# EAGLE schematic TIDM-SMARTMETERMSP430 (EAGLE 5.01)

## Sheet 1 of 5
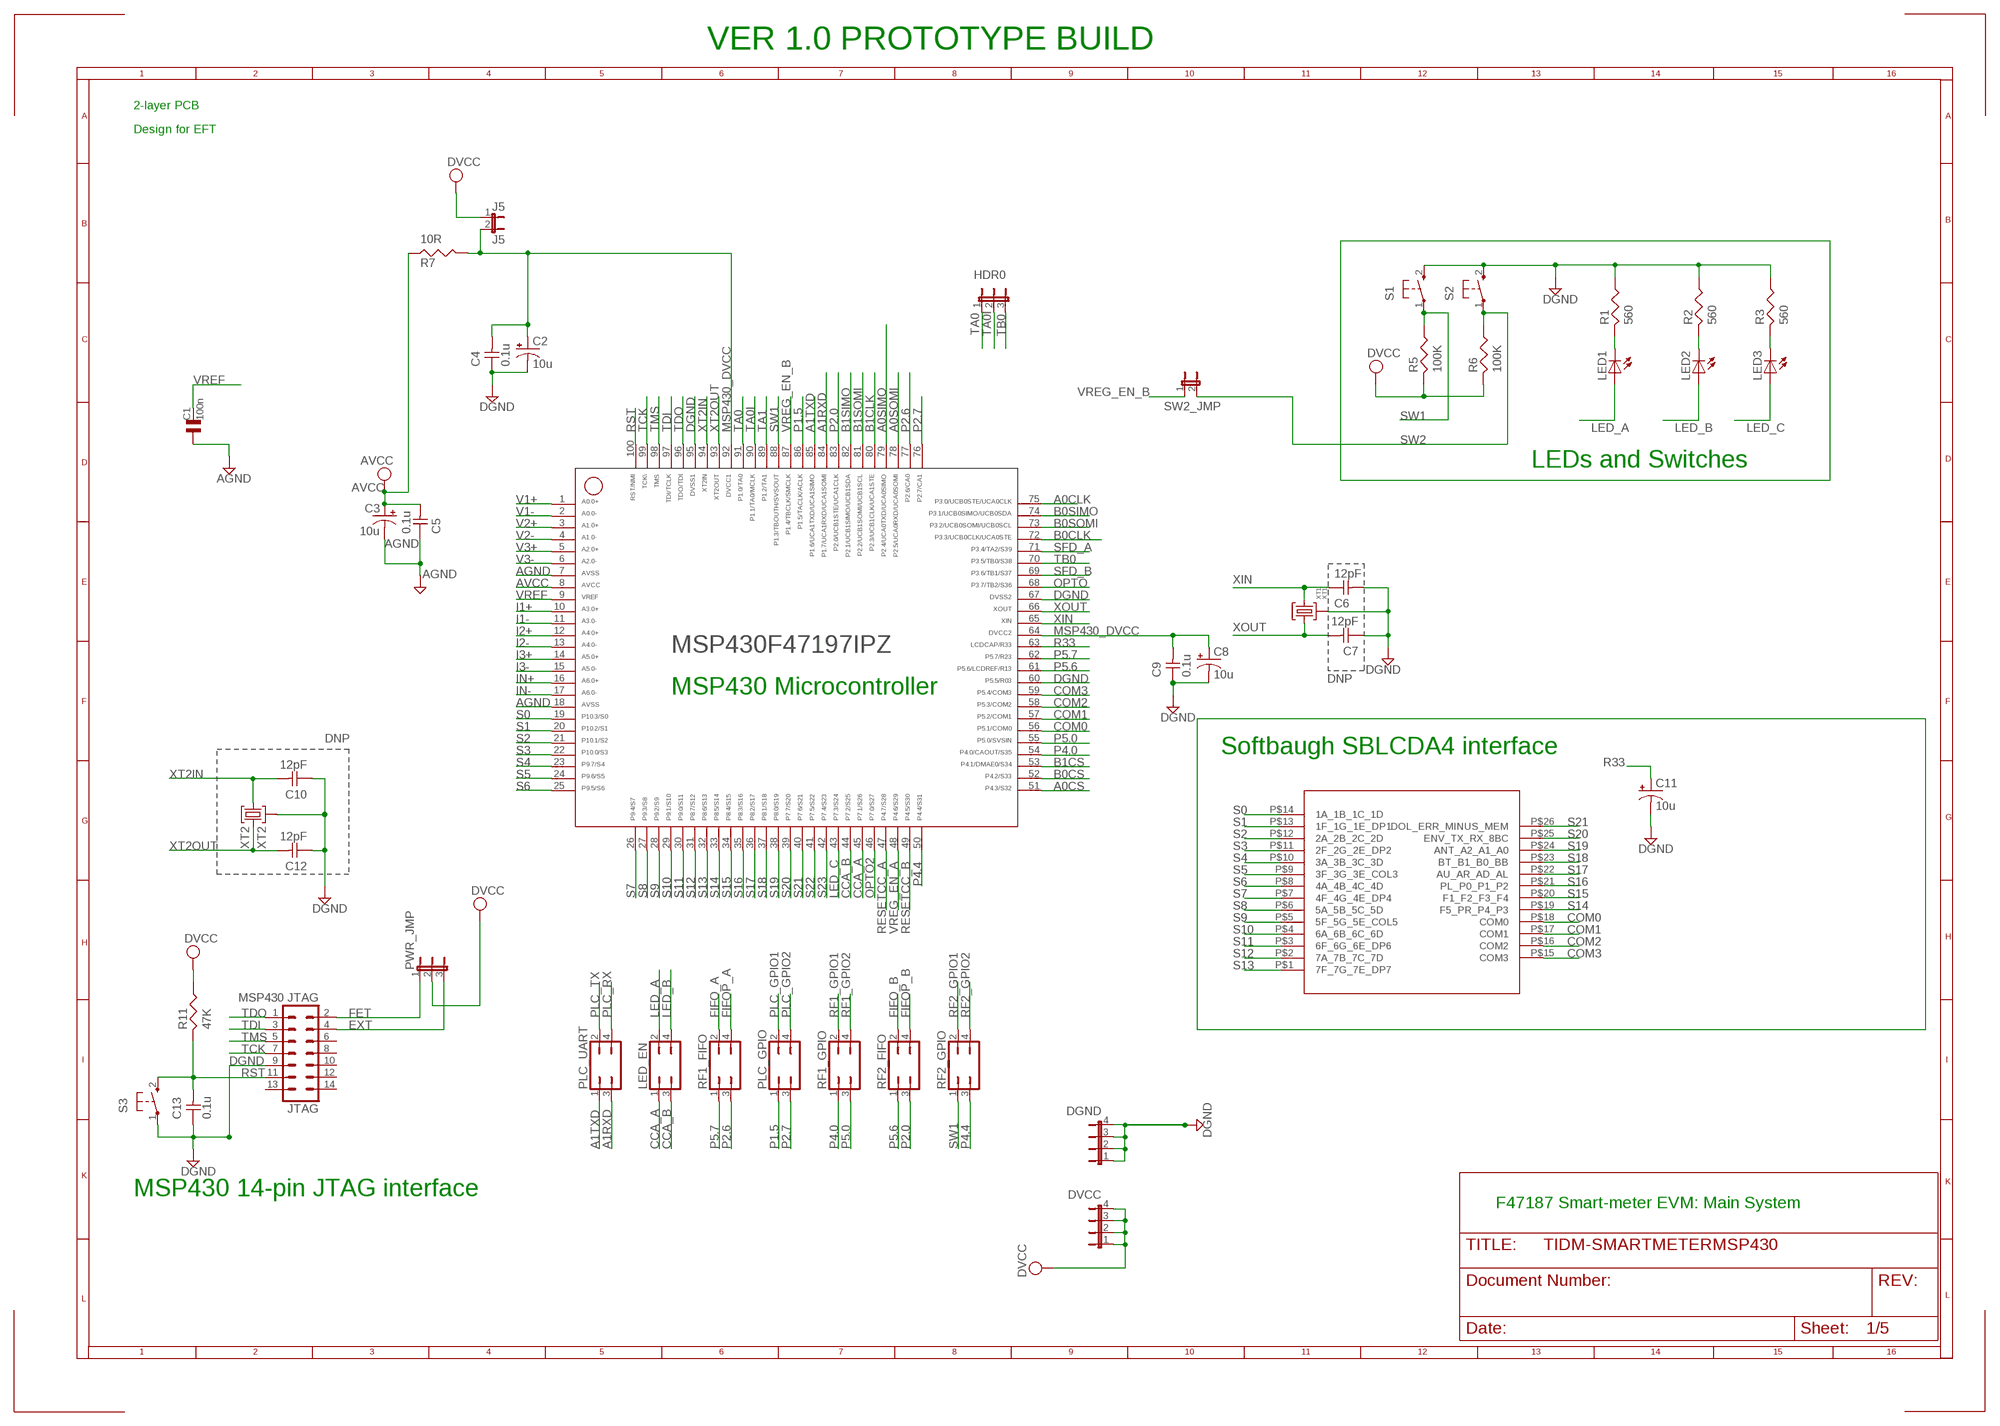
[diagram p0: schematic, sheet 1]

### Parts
C1  100n  C  [0805]
C2  10u  CPOL-USCT3216  [CT3216]
C3  10u  CPOL-USCT3216  [CT3216]
C4  0.1u  CAP-NP0805  [C0805]
C5  0.1u  CAP-NP0805  [C0805]
C6  12pF  CAP-NP0805  [C0805]
C7  12pF  CAP-NP0805  [C0805]
C8  10u  CPOL-USCT3216  [CT3216]
C9  0.1u  CAP-NP0805  [C0805]
C10  12pF  CAP-NP0805  [C0805]
C11  10u  CPOL-USCT3216  [CT3216]
C12  12pF  CAP-NP0805  [C0805]
C13  0.1u  CAP-NP0805  [C0805]
DGND  GND_JMP  JP4E  [JP4]
DVCC  JP4E  [JP4]
HDR0  JP2E  [JP2]
J5  J5  JP1E  [JP1]
JTAG  MSP430 JTAG  ML14  [ML14]
LCD1  SBLCDA4  [SBLCDA4]
LED1  LEDCHIPLED_0805  [CHIPLED_0805]
LED2  LEDCHIPLED_0805  [CHIPLED_0805]
LED3  LEDCHIPLED_0805  [CHIPLED_0805]
LED_EN  JP2Q  [JP2Q]
MSP430F47187  MSP430F471X7PZ100  [PZ100]
PLC_GPIO  JP2Q  [JP2Q]
PLC_UART  JP2Q  [JP2Q]
PWR_JMP  JP2E  [JP2]
R1  560  RES0805  [R0805]
R2  560  RES0805  [R0805]
R3  560  RES0805  [R0805]
R5  100K  RES0805  [R0805]
R6  100K  RES0805  [R0805]
R7  10R  RES0805  [R0805]
R11  47K  RES0805  [R0805]
RF1_FIFO  JP2Q  [JP2Q]
RF1_GPIO  JP2Q  [JP2Q]
RF2_FIFO  JP2Q  [JP2Q]
RF2_GPIO  JP2Q  [JP2Q]
S1  PB  [PBTH]
S2  PB  [PBTH]
S3  PB  [PBTH]
SW2_JMP  JP1E  [JP1]
XT1  XT1  CM200T  [CM200T]
XT2  XT2  X905  [X905]

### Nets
A0CLK: MSP430F47187.75 ; also sheet 4
A0CS: MSP430F47187.51 ; also sheet 4
A0SIMO: MSP430F47187.79 ; also sheet 4
A0SOMI: MSP430F47187.78 ; also sheet 4
A1RXD: MSP430F47187.84 PLC_UART.3 ; also sheet 4
A1TXD: MSP430F47187.85 PLC_UART.1 ; also sheet 4
AGND: C1.1 C3.- C5.1 MSP430F47187.7 MSP430F47187.18 ; also sheet 2
AVCC: C3.+ C5.2 MSP430F47187.8 R7.2 ; also sheet 2
B0CLK: MSP430F47187.72 ; also sheet 4
B0CS: MSP430F47187.52 ; also sheet 4
B0SIMO: MSP430F47187.74 ; also sheet 4
B0SOMI: MSP430F47187.73 ; also sheet 4
B1CLK: MSP430F47187.80 ; also sheet 5
B1CS: MSP430F47187.53 ; also sheet 5
B1SIMO: MSP430F47187.82 ; also sheet 5
B1SOMI: MSP430F47187.81 ; also sheet 5
CCA_A: LED_EN.1 MSP430F47187.45 ; also sheet 4
CCA_B: LED_EN.3 MSP430F47187.44 ; also sheet 4
COM0: LCD1.P$18(COM0) MSP430F47187.56
COM1: LCD1.P$17(COM1) MSP430F47187.57
COM2: LCD1.P$16(COM2) MSP430F47187.58
COM3: LCD1.P$15(COM3) MSP430F47187.59
DGND: C2.- C4.1 C6.2 C7.1 C8.- C9.1 C10.1 C11.- C12.1 C13.1 DGND.1 DGND.2 DGND.3 DGND.4 JTAG.9 MSP430F47187.60 MSP430F47187.67 MSP430F47187.95 R1.1 R2.1 R3.1 S1.2(S) S2.2(S) S3.1(P) XT1.P3 XT2.2 ; also sheet 3,4,5
DVCC: DVCC.1 DVCC.2 DVCC.3 DVCC.4 J5.1 PWR_JMP.2 R5.2 R6.2 R11.1 ; also sheet 3,4,5
EXT: JTAG.4 PWR_JMP.3
FET: JTAG.2 PWR_JMP.1
FIFO_A: RF1_FIFO.2 ; also sheet 4
FIFO_B: RF2_FIFO.2 ; also sheet 4
FIFOP_A: RF1_FIFO.4 ; also sheet 4
FIFOP_B: RF2_FIFO.4 ; also sheet 4
I1+: MSP430F47187.10 ; also sheet 2
I1-: MSP430F47187.11 ; also sheet 2
I2+: MSP430F47187.12 ; also sheet 2
I2-: MSP430F47187.13 ; also sheet 2
I3+: MSP430F47187.14 ; also sheet 2
I3-: MSP430F47187.15 ; also sheet 2
IN+: MSP430F47187.16 ; also sheet 2
IN-: MSP430F47187.17 ; also sheet 2
LED_A: LED1.A LED_EN.2
LED_B: LED2.A LED_EN.4
LED_C: LED3.A MSP430F47187.43
MSP430_DVCC: C2.+ C4.2 C8.+ C9.2 J5.2 MSP430F47187.64 MSP430F47187.92 R7.1
N$4: LED1.C R1.2
N$7: LED2.C R2.2
N$30: LED3.C R3.2
OPTO: MSP430F47187.68 ; also sheet 4
OPTO2: MSP430F47187.46 ; also sheet 4
P1.5: MSP430F47187.86 PLC_GPIO.1
P2.0: MSP430F47187.83 RF2_FIFO.3
P2.6: MSP430F47187.77 RF1_FIFO.3
P2.7: MSP430F47187.76 PLC_GPIO.3
P4.0: MSP430F47187.54 RF1_GPIO.1
P4.4: MSP430F47187.50 RF2_GPIO.3
P5.0: MSP430F47187.55 RF1_GPIO.3
P5.6: MSP430F47187.61 RF2_FIFO.1
P5.7: MSP430F47187.62 RF1_FIFO.1
PLC_GPIO1: PLC_GPIO.2 ; also sheet 5
PLC_GPIO2: PLC_GPIO.4 ; also sheet 5
PLC_RX: PLC_UART.4 ; also sheet 3,4,5
PLC_TX: PLC_UART.2 ; also sheet 3,4,5
R33: C11.+ MSP430F47187.63
RESETCC_A: MSP430F47187.47 ; also sheet 4
RESETCC_B: MSP430F47187.49 ; also sheet 4
RF1_GPIO1: RF1_GPIO.2 ; also sheet 4
RF1_GPIO2: RF1_GPIO.4 ; also sheet 4
RF2_GPIO1: RF2_GPIO.2 ; also sheet 4
RF2_GPIO2: RF2_GPIO.4 ; also sheet 4
RST: C13.2 JTAG.11 MSP430F47187.100 R11.2 S3.2(S)
S0: LCD1.P$14(1A_1B_1C_1D) MSP430F47187.19
S1: LCD1.P$13(1F_1G_1E_DP1) MSP430F47187.20
S2: LCD1.P$12(2A_2B_2C_2D) MSP430F47187.21
S3: LCD1.P$11(2F_2G_2E_DP2) MSP430F47187.22
S4: LCD1.P$10(3A_3B_3C_3D) MSP430F47187.23
S5: LCD1.P$9(3F_3G_3E_COL3) MSP430F47187.24
S6: LCD1.P$8(4A_4B_4C_4D) MSP430F47187.25
S7: LCD1.P$7(4F_4G_4E_DP4) MSP430F47187.26
S8: LCD1.P$6(5A_5B_5C_5D) MSP430F47187.27
S9: LCD1.P$5(5F_5G_5E_COL5) MSP430F47187.28
S10: LCD1.P$4(6A_6B_6C_6D) MSP430F47187.29
S11: LCD1.P$3(6F_6G_6E_DP6) MSP430F47187.30
S12: LCD1.P$2(7A_7B_7C_7D) MSP430F47187.31
S13: LCD1.P$1(7F_7G_7E_DP7) MSP430F47187.32
S14: LCD1.P$19(F5_PR_P4_P3) MSP430F47187.33
S15: LCD1.P$20(F1_F2_F3_F4) MSP430F47187.34
S16: LCD1.P$21(PL_P0_P1_P2) MSP430F47187.35
S17: LCD1.P$22(AU_AR_AD_AL) MSP430F47187.36
S18: LCD1.P$23(BT_B1_B0_BB) MSP430F47187.37
S19: LCD1.P$24(ANT_A2_A1_A0) MSP430F47187.38
S20: LCD1.P$25(ENV_TX_RX_8BC) MSP430F47187.39
S21: LCD1.P$26(DOL_ERR_MINUS_MEM) MSP430F47187.40
S22: MSP430F47187.41
S23: MSP430F47187.42
SFD_A: MSP430F47187.71 ; also sheet 4
SFD_B: MSP430F47187.69 ; also sheet 4
SW1: MSP430F47187.88 R5.1 RF2_GPIO.1 S1.1(P)
SW2: R6.1 S2.1(P) SW2_JMP.2
TA0: HDR0.1 MSP430F47187.91
TA0I: HDR0.2 MSP430F47187.90
TA1: MSP430F47187.89 ; also sheet 5
TB0: HDR0.3 MSP430F47187.70
TCK: JTAG.7 MSP430F47187.99
TDI: JTAG.3 MSP430F47187.97
TDO: JTAG.1 MSP430F47187.96
TMS: JTAG.5 MSP430F47187.98
V1+: MSP430F47187.1 ; also sheet 2
V1-: MSP430F47187.2 ; also sheet 2
V2+: MSP430F47187.3 ; also sheet 2
V2-: MSP430F47187.4 ; also sheet 2
V3+: MSP430F47187.5 ; also sheet 2
V3-: MSP430F47187.6 ; also sheet 2
VREF: C1.2 MSP430F47187.9 ; also sheet 2
VREG_EN_A: MSP430F47187.48 ; also sheet 4
VREG_EN_B: MSP430F47187.87 SW2_JMP.1 ; also sheet 4
XIN: C6.1 MSP430F47187.65 XT1.P2
XOUT: C7.2 MSP430F47187.66 XT1.P1
XT2IN: C10.2 MSP430F47187.94 XT2.1
XT2OUT: C12.2 MSP430F47187.93 XT2.3
Unconnected: JTAG.6 JTAG.8 JTAG.10 JTAG.12 JTAG.13 JTAG.14

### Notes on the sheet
- VER 1.0 PROTOTYPE BUILD
- 2-layer PCB
- Design for EFT
- LEDs and Switches
- DNP
- MSP430 Microcontroller
- DNP
- Softbaugh SBLCDA4 interface
- MSP430 14-pin JTAG interface
- F47187 Smart-meter EVM: Main System

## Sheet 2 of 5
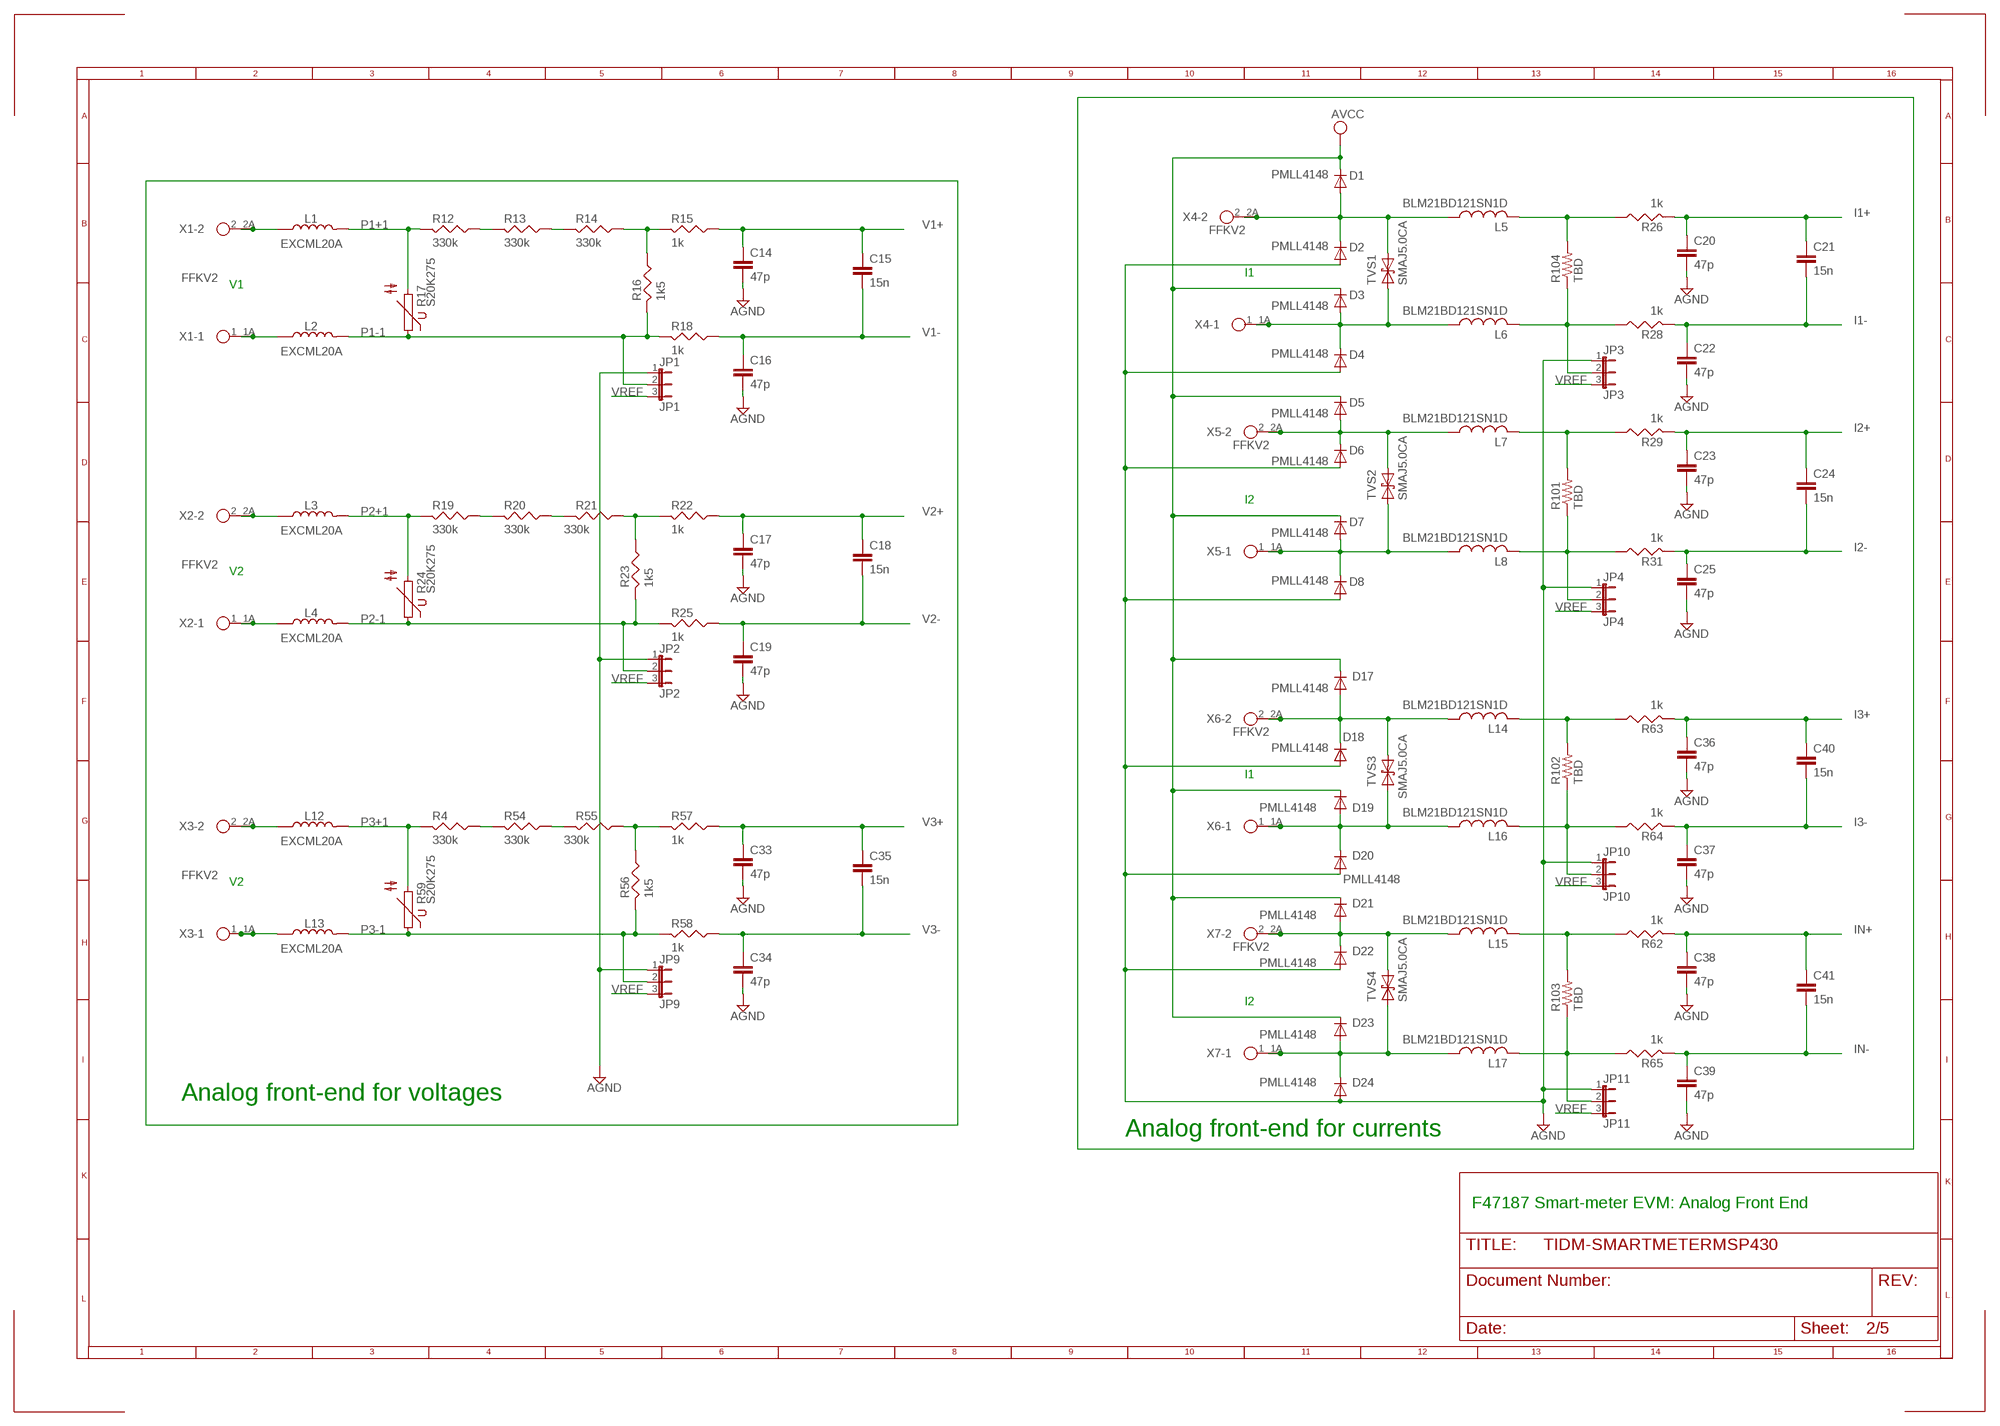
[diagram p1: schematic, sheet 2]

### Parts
C14  47p  C-EUC0805  [C0805]
C15  15n  C-EUC0805  [C0805]
C16  47p  C-EUC0805  [C0805]
C17  47p  C-EUC0805  [C0805]
C18  15n  C-EUC0805  [C0805]
C19  47p  C-EUC0805  [C0805]
C20  47p  C-EUC0805  [C0805]
C21  15n  C-EUC0805  [C0805]
C22  47p  C-EUC0805  [C0805]
C23  47p  C-EUC0805  [C0805]
C24  15n  C-EUC0805  [C0805]
C25  47p  C-EUC0805  [C0805]
C33  47p  C-EUC0805  [C0805]
C34  47p  C-EUC0805  [C0805]
C35  15n  C-EUC0805  [C0805]
C36  47p  C-EUC0805  [C0805]
C37  47p  C-EUC0805  [C0805]
C38  47p  C-EUC0805  [C0805]
C39  47p  C-EUC0805  [C0805]
C40  15n  C-EUC0805  [C0805]
C41  15n  C-EUC0805  [C0805]
D1  PMLL4148  [SOD80C]
D2  PMLL4148  [SOD80C]
D3  PMLL4148  [SOD80C]
D4  PMLL4148  [SOD80C]
D5  PMLL4148  [SOD80C]
D6  PMLL4148  [SOD80C]
D7  PMLL4148  [SOD80C]
D8  PMLL4148  [SOD80C]
D17  PMLL4148  [SOD80C]
D18  PMLL4148  [SOD80C]
D19  PMLL4148  [SOD80C]
D20  PMLL4148  [SOD80C]
D21  PMLL4148  [SOD80C]
D22  PMLL4148  [SOD80C]
D23  PMLL4148  [SOD80C]
D24  PMLL4148  [SOD80C]
JP1  JP1  JP2E  [JP2]
JP2  JP2  JP2E  [JP2]
JP3  JP3  JP2E  [JP2]
JP4  JP4  JP2E  [JP2]
JP9  JP9  JP2E  [JP2]
JP10  JP10  JP2E  [JP2]
JP11  JP11  JP2E  [JP2]
L1  EXCML20A  EXCELSA390805  [R0805]
L2  EXCML20A  EXCELSA390805  [R0805]
L3  EXCML20A  EXCELSA390805  [R0805]
L4  EXCML20A  EXCELSA390805  [R0805]
L5  BLM21BD121SN1D  L-US08050805  [0805]
L6  BLM21BD121SN1D  L-US08050805  [0805]
L7  BLM21BD121SN1D  L-US08050805  [0805]
L8  BLM21BD121SN1D  L-US08050805  [0805]
L12  EXCML20A  EXCELSA390805  [R0805]
L13  EXCML20A  EXCELSA390805  [R0805]
L14  BLM21BD121SN1D  L-US08050805  [0805]
L15  BLM21BD121SN1D  L-US08050805  [0805]
L16  BLM21BD121SN1D  L-US08050805  [0805]
L17  BLM21BD121SN1D  L-US08050805  [0805]
R4  330k  RES0805  [R0805]
R12  330k  RES0805  [R0805]
R13  330k  RES0805  [R0805]
R14  330k  RES0805  [R0805]
R15  1k  RES0805  [R0805]
R16  1k5  RES0805  [R0805]
R17  S20K275  [S20K275]
R18  1k  RES0805  [R0805]
R19  330k  RES0805  [R0805]
R20  330k  RES0805  [R0805]
R21  330k  RES0805  [R0805]
R22  1k  RES0805  [R0805]
R23  1k5  RES0805  [R0805]
R24  S20K275  [S20K275]
R25  1k  RES0805  [R0805]
R26  1k  RES0805  [R0805]
R28  1k  RES0805  [R0805]
R29  1k  RES0805  [R0805]
R31  1k  RES0805  [R0805]
R54  330k  RES0805  [R0805]
R55  330k  RES0805  [R0805]
R56  1k5  RES0805  [R0805]
R57  1k  RES0805  [R0805]
R58  1k  RES0805  [R0805]
R59  S20K275  [S20K275]
R62  1k  RES0805  [R0805]
R63  1k  RES0805  [R0805]
R64  1k  RES0805  [R0805]
R65  1k  RES0805  [R0805]
R101  TBD  R-US_0207/2V  [0207/2V]
R102  TBD  R-US_0207/2V  [0207/2V]
R103  TBD  R-US_0207/2V  [0207/2V]
R104  TBD  R-US_0207/2V  [0207/2V]
TVS1  SMAJ5.0CA  [DO214AC]
TVS2  SMAJ5.0CA  [DO214AC]
TVS3  SMAJ5.0CA  [DO214AC]
TVS4  SMAJ5.0CA  [DO214AC]
X1  FFKV2  [FFKV2]
X2  FFKV2  [FFKV2]
X3  FFKV2  [FFKV2]
X4  FFKV2  [FFKV2]
X5  FFKV2  [FFKV2]
X6  FFKV2  [FFKV2]
X7  FFKV2  [FFKV2]

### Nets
AGND: C14.2 C16.2 C17.2 C19.2 C20.2 C22.2 C23.2 C25.2 C33.2 C34.2 C36.2 C37.2 C38.2 C39.2 D2.A D4.A D6.A D8.A D18.A D20.A D22.A D24.A JP1.1 JP2.1 JP3.1 JP4.1 JP9.1 JP10.1 JP11.1 ; also sheet 1
AVCC: D1.C D3.C D5.C D7.C D17.C D19.C D21.C D23.C ; also sheet 1
I1+: C20.1 C21.1 R26.2 ; also sheet 1
I1-: C21.2 C22.1 R28.2 ; also sheet 1
I2+: C23.1 C24.1 R29.2 ; also sheet 1
I2-: C24.2 C25.1 R31.2 ; also sheet 1
I3+: C36.1 C40.1 R63.2 ; also sheet 1
I3-: C37.1 C40.2 R64.2 ; also sheet 1
IN+: C38.1 C41.1 R62.2 ; also sheet 1
IN-: C39.1 C41.2 R65.2 ; also sheet 1
IS1+: D1.A D2.C L5.1 TVS1.C(K) X4.2 X4.2A
IS2+: D5.A D6.C L7.1 TVS2.C(K) X5.2 X5.2A
N$8: R12.1 R13.2
N$13: R13.1 R14.2
N$14: R14.1 R15.2 R16.1
N$15: R19.1 R20.2
N$16: R20.1 R21.2
N$19: R21.1 R22.2 R23.1
N$27: R4.1 R54.2
N$28: R54.1 R55.2
N$29: R55.1 R56.1 R57.2
N$31: L7.2 R29.1 R101.2
N$32: L5.2 R26.1 R104.2
N$33: L15.2 R62.1 R103.2
N$34: L14.2 R63.1 R102.2
N$35: JP10.2 L16.2 R64.1 R102.1
N$36: JP11.2 L17.2 R65.1 R103.1
N$41: D3.A D4.C L6.1 TVS1.A X4.1 X4.1A
N$43: D23.A D24.C L17.1 TVS4.A X7.1 X7.1A
N$47: D17.A D18.C L14.1 TVS3.C(K) X6.2 X6.2A
N$48: D7.A D8.C L8.1 TVS2.A X5.1 X5.1A
N$49: D19.A D20.C L16.1 TVS3.A X6.1 X6.1A
N$72: D21.A D22.C L15.1 TVS4.C(K) X7.2 X7.2A
N$202: JP3.2 L6.2 R28.1 R104.1
N$229: JP4.2 L8.2 R31.1 R101.1
P1+: L1.1 X1.2 X1.2A
P1+1: L1.2 R12.2 R17.2 ; also sheet 3,5
P1-: L2.1 X1.1 X1.1A
P1-1: JP1.2 L2.2 R16.2 R17.1 R18.2 ; also sheet 3,5
P2+: L3.1 X2.2 X2.2A
P2+1: L3.2 R19.2 R24.2 ; also sheet 5
P2-: L4.1 X2.1 X2.1A
P2-1: JP2.2 L4.2 R23.2 R24.1 R25.2
P3+: L12.1 X3.2 X3.2A
P3+1: L12.2 R4.2 R59.2 ; also sheet 5
P3-: L13.1 X3.1 X3.1A
P3-1: JP9.2 L13.2 R56.2 R58.2 R59.1
V1+: C14.1 C15.1 R15.1 ; also sheet 1
V1-: C15.2 C16.1 R18.1 ; also sheet 1
V2+: C17.1 C18.1 R22.1 ; also sheet 1
V2-: C18.2 C19.1 R25.1 ; also sheet 1
V3+: C33.1 C35.1 R57.1 ; also sheet 1
V3-: C34.1 C35.2 R58.1 ; also sheet 1
VREF: JP1.3 JP2.3 JP3.3 JP4.3 JP9.3 JP10.3 JP11.3 ; also sheet 1

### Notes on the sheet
- I1
- V1
- I2
- V2
- I1
- V2
- I2
- Analog front-end for voltages
- Analog front-end for currents
- F47187 Smart-meter EVM: Analog Front End

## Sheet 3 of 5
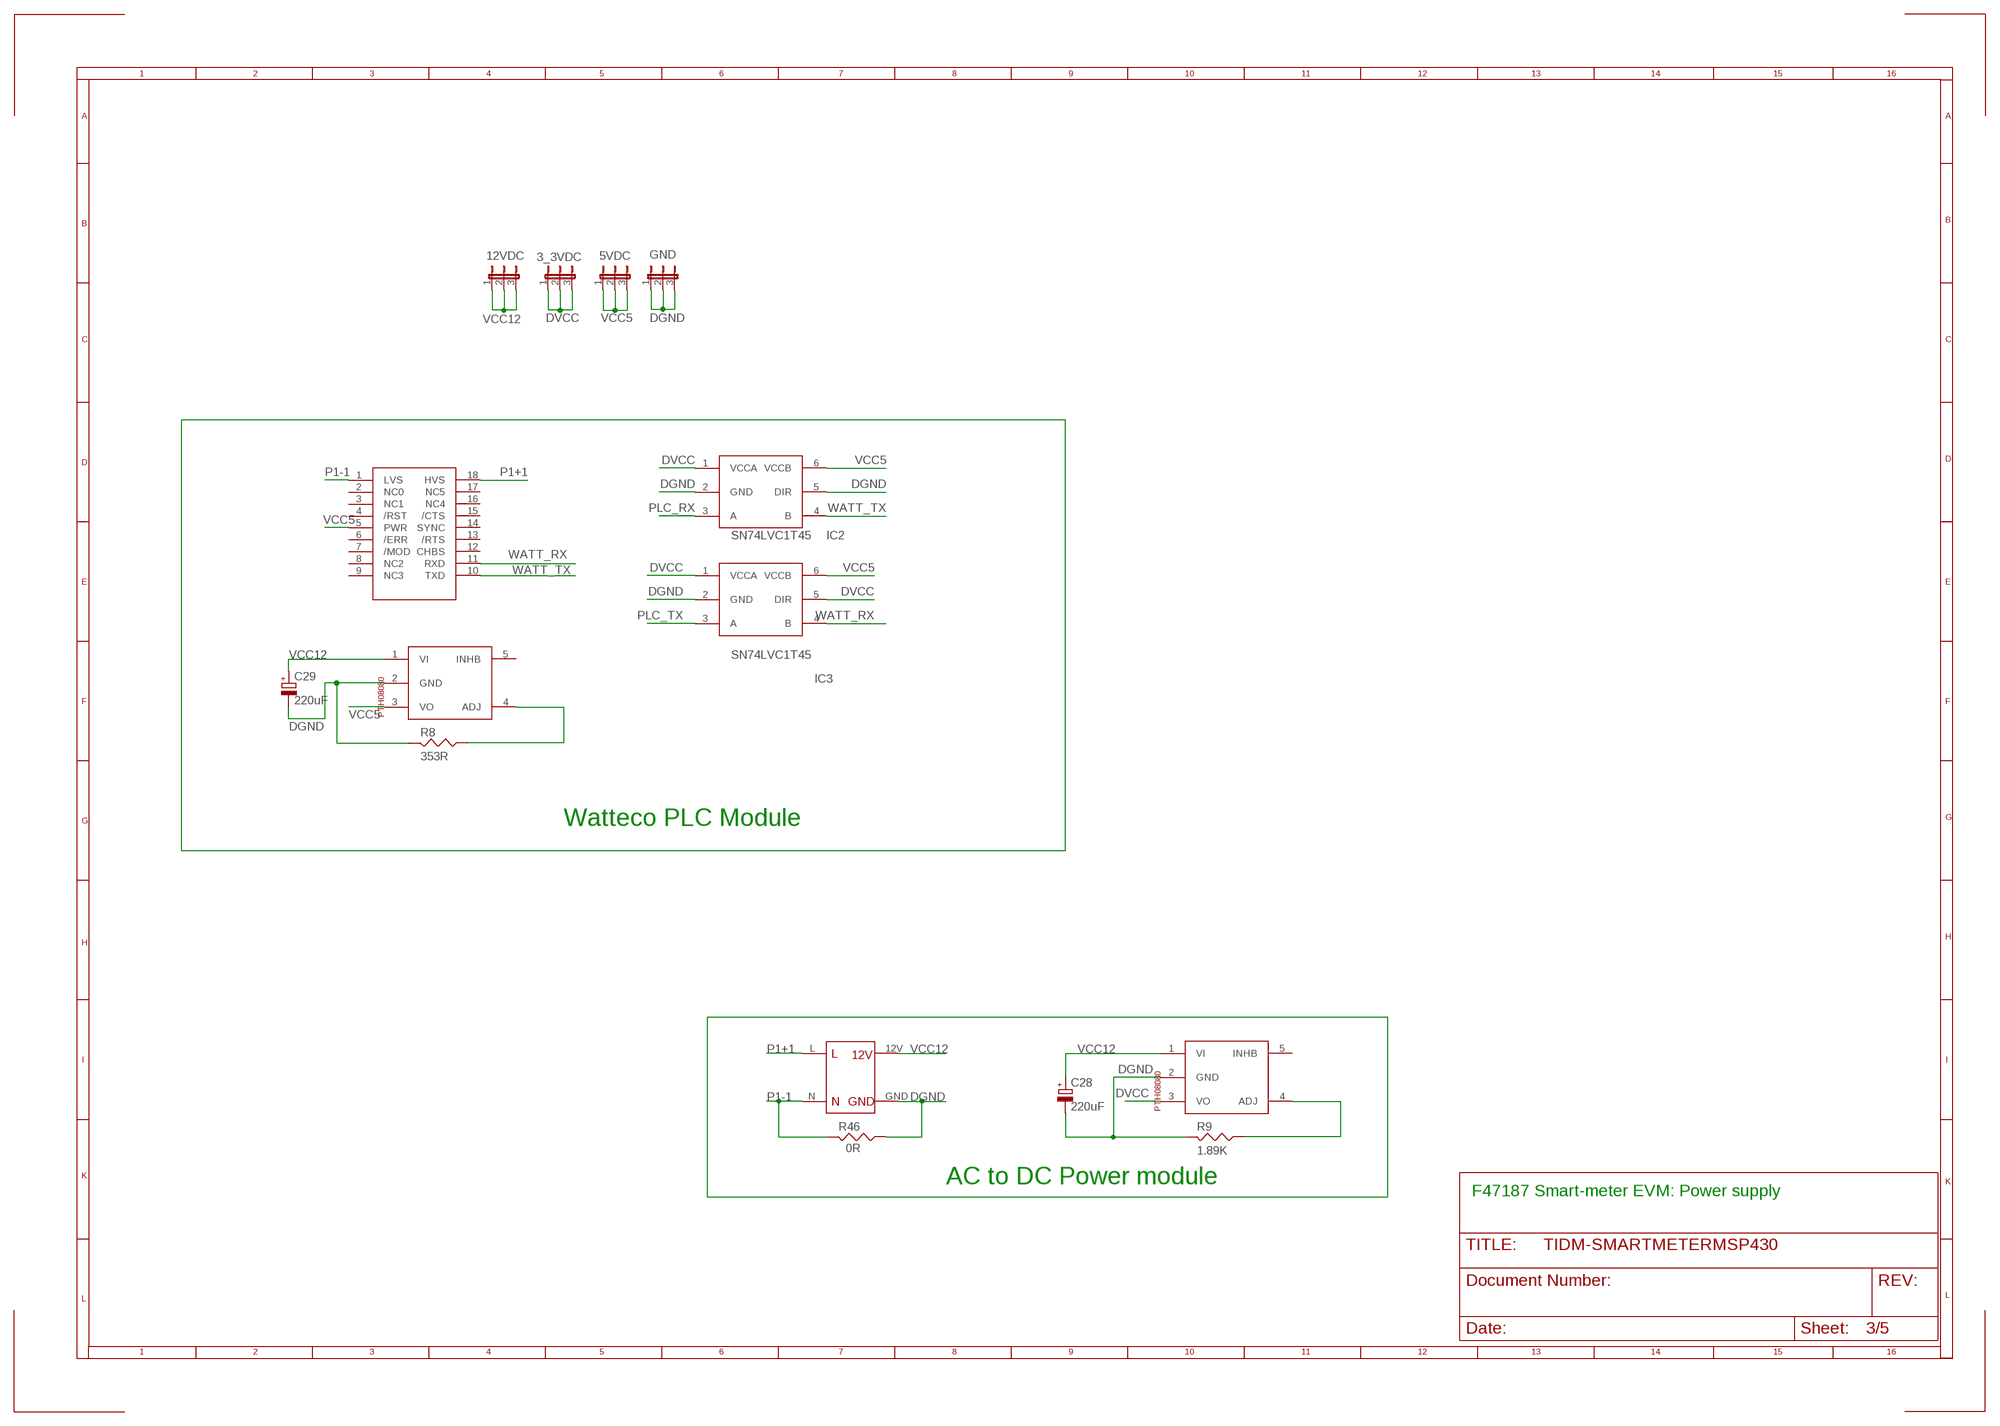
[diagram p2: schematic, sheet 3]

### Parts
3_3VDC  JP2E  [JP2]
5VDC  JP2E  [JP2]
12VDC  JP2E  [JP2]
C28  220uF  CPOL-EUE2-5  [E2-5]
C29  220uF  CPOL-EUE2-5  [E2-5]
GND  JP2E  [JP2]
R8  353R  RES0805  [R0805]
R9  1.89K  RES0805  [R0805]
R46  0R  RES0805  [R0805]
U$4  AC_DC_12V  [AC_DC_12V]
U$5  PTH08080  [PTH08080]
U$6  WATT_PULSE  [WATT_PULSE]
U$7  PTH08080  [PTH08080]
U$8  741T45  [DBV_R-PDSO-G6]
U$9  741T45  [DBV_R-PDSO-G6]

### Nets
DGND: C28.- C29.- GND.1 GND.2 GND.3 R8.2 R9.2 R46.1 U$4.GND U$5.2(GND) U$7.2(GND) U$8.2(GND) U$8.5(DIR) U$9.2(GND) ; also sheet 1,4,5
DVCC: 3_3VDC.1 3_3VDC.2 3_3VDC.3 U$7.3(VO) U$8.1(VCCA) U$9.1(VCCA) U$9.5(DIR) ; also sheet 1,4,5
N$74: R9.1 U$7.4(ADJ)
N$115: R8.1 U$5.4(ADJ)
P1+1: U$4.L U$6.18(HVS) ; also sheet 2,5
P1-1: R46.2 U$4.N U$6.1(LVS) ; also sheet 2,5
PLC_RX: U$8.3(A) ; also sheet 1,4,5
PLC_TX: U$9.3(A) ; also sheet 1,4,5
VCC5: 5VDC.1 5VDC.2 5VDC.3 U$5.3(VO) U$6.5(PWR) U$8.6(VCCB) U$9.6(VCCB)
VCC12: 12VDC.1 12VDC.2 12VDC.3 C28.+ C29.+ U$4.12V U$5.1(VI) U$7.1(VI) ; also sheet 5
WATT_RX: U$6.11(RXD) U$9.4(B)
WATT_TX: U$6.10(TXD) U$8.4(B)
Unconnected: U$5.5(INHB) U$6.2(NC0) U$6.3(NC1) U$6.4(/RST) U$6.6(/ERR) U$6.7(/MOD) U$6.8(NC2) U$6.9(NC3) U$6.12(CHBS) U$6.13(/RTS) U$6.14(SYNC) U$6.15(/CTS) U$6.16(NC4) U$6.17(NC5) U$7.5(INHB)

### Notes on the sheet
- SN74LVC1T45 | IC2
- SN74LVC1T45
- IC3
- Watteco PLC Module
- AC to DC Power module
- F47187 Smart-meter EVM: Power supply

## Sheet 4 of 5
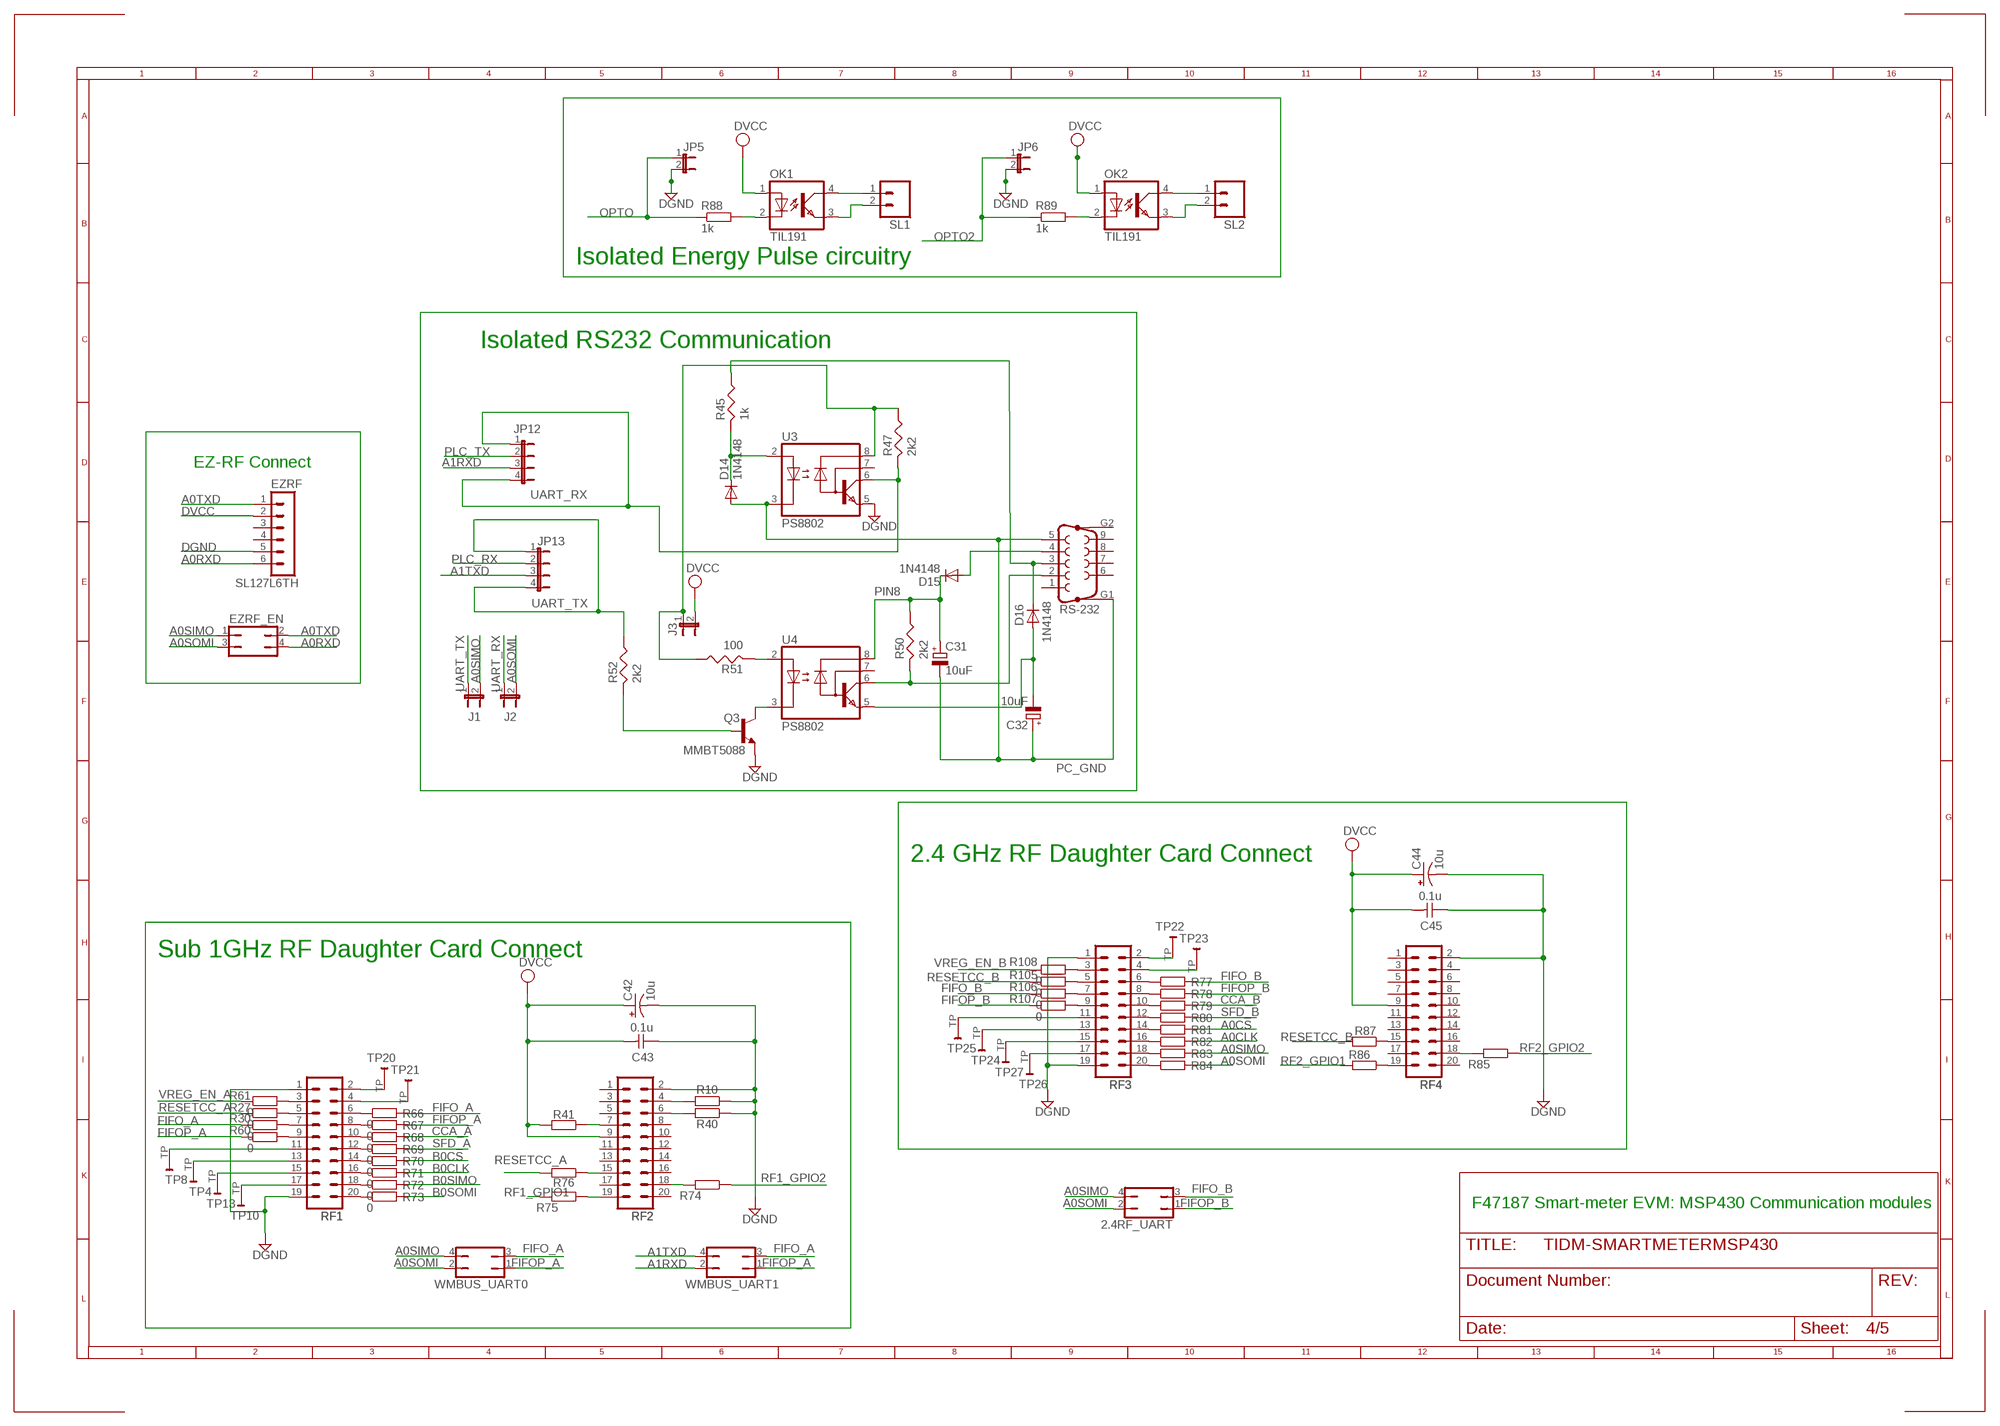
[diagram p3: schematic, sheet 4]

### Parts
2.4RF_UART  JP2Q  [JP2Q]
C31  10uF  CPOL-EUB/3528-21W  [B/3528-21W]
C32  10uF  CPOL-EUB/3528-21W  [B/3528-21W]
C42  10u  CPOL-USCT3216  [CT3216]
C43  0.1u  CAP-NP0805  [C0805]
C44  10u  CPOL-USCT3216  [CT3216]
C45  0.1u  CAP-NP0805  [C0805]
D14  1N4148  DIODE-SOD80C  [SOD80C]
D15  1N4148  DIODE-SOD80C  [SOD80C]
D16  1N4148  DIODE-SOD80C  [SOD80C]
EZRF  SL127L6TH  [SL127L6_MPE]
EZRF_EN  JP2Q  [JP2Q]
J1  JP1E  [JP1]
J2  JP1E  [JP1]
J3  JP1E  [JP1]
JP5  JP1E  [JP1]
JP6  JP1E  [JP1]
JP12  JP4E  [JP4]
JP13  JP4E  [JP4]
OK1  TIL191  [DIL04]
OK2  TIL191  [DIL04]
Q3  BC807SMD  [SOT23-BEC@1]
R10  0  R-EU_R0603  [R0603]
R27  0  R-EU_R0603  [R0603]
R30  0  R-EU_R0603  [R0603]
R40  0  R-EU_R0603  [R0603]
R41  0  R-EU_R0603  [R0603]
R45  1k  RES0805  [R0805]
R47  2k2  RES0805  [R0805]
R50  2k2  RES0805  [R0805]
R51  100  RES0805  [R0805]
R52  2k2  RES0805  [R0805]
R60  0  R-EU_R0603  [R0603]
R61  0  R-EU_R0603  [R0603]
R66  0  R-EU_R0603  [R0603]
R67  0  R-EU_R0603  [R0603]
R68  0  R-EU_R0603  [R0603]
R69  0  R-EU_R0603  [R0603]
R70  0  R-EU_R0603  [R0603]
R71  0  R-EU_R0603  [R0603]
R72  0  R-EU_R0603  [R0603]
R73  0  R-EU_R0603  [R0603]
R74  0  R-EU_R0603  [R0603]
R75  0  R-EU_R0603  [R0603]
R76  0  R-EU_R0603  [R0603]
R77  0  R-EU_R0603  [R0603]
R78  0  R-EU_R0603  [R0603]
R79  0  R-EU_R0603  [R0603]
R80  0  R-EU_R0603  [R0603]
R81  0  R-EU_R0603  [R0603]
R82  0  R-EU_R0603  [R0603]
R83  0  R-EU_R0603  [R0603]
R84  0  R-EU_R0603  [R0603]
R85  0  R-EU_R0603  [R0603]
R86  0  R-EU_R0603  [R0603]
R87  0  R-EU_R0603  [R0603]
R88  1k  R-EU_M0805  [M0805]
R89  1k  R-EU_M0805  [M0805]
R105  0  R-EU_R0603  [R0603]
R106  0  R-EU_R0603  [R0603]
R107  0  R-EU_R0805  [R0805]
R108  0  R-EU_R0603  [R0603]
RF1  TFM-110-02-SM-D-A-K  [TFM-110-02-SM-D-A-K]
RF2  TFM-110-02-SM-D-A-K  [TFM-110-02-SM-D-A-K]
RF3  TFM-110-02-SM-D-A-K  [TFM-110-02-SM-D-A-K]
RF4  TFM-110-02-SM-D-A-K  [TFM-110-02-SM-D-A-K]
RS-232  F09VP  [F09VP]
SL1  M02  [02P]
SL2  M02  [02P]
TP4  TST_PNT  [TST_PNT]
TP8  TST_PNT  [TST_PNT]
TP10  TST_PNT  [TST_PNT]
TP13  TST_PNT  [TST_PNT]
TP20  TST_PNT  [TST_PNT]
TP21  TST_PNT  [TST_PNT]
TP22  TST_PNT  [TST_PNT]
TP23  TST_PNT  [TST_PNT]
TP24  TST_PNT  [TST_PNT]
TP25  TST_PNT  [TST_PNT]
TP26  TST_PNT  [TST_PNT]
TP27  TST_PNT  [TST_PNT]
U3  PS8802  [SO08]
U4  PS8802  [SO08]
WMBUS_UART0  JP2Q  [JP2Q]
WMBUS_UART1  JP2Q  [JP2Q]

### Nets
A0CLK: R82.2 ; also sheet 1
A0CS: R81.2 ; also sheet 1
A0RXD: EZRF.6 EZRF_EN.4
A0SIMO: 2.4RF_UART.4 EZRF_EN.1 J1.2 R83.2 WMBUS_UART0.4 ; also sheet 1
A0SOMI: 2.4RF_UART.2 EZRF_EN.3 J2.2 R84.2 WMBUS_UART0.2 ; also sheet 1
A0TXD: EZRF.1 EZRF_EN.2
A1RXD: JP12.3 WMBUS_UART1.2 ; also sheet 1
A1TXD: JP13.3 WMBUS_UART1.4 ; also sheet 1
B0CLK: R71.2 ; also sheet 1
B0CS: R70.2 ; also sheet 1
B0SIMO: R72.2 ; also sheet 1
B0SOMI: R73.2 ; also sheet 1
CCA_A: R68.2 ; also sheet 1
CCA_B: R79.2 ; also sheet 1
DGND: C42.- C43.1 C44.- C45.1 EZRF.5 JP5.2 JP6.2 Q3.E R10.1 R40.1 RF1.1 RF1.19 RF2.2 RF3.1 RF3.19 RF4.2 U3.5(GND) ; also sheet 1,3,5
DVCC: C42.+ C43.2 C44.+ C45.2 EZRF.2 J3.2 OK1.1(A) OK2.1(A) R41.2 RF2.9 RF4.9 ; also sheet 1,3,5
FIFO: RF1.2 TP20.TP(-)
FIFO1: RF3.2 TP22.TP(-)
FIFO_A: R30.1 R66.2 WMBUS_UART0.3 WMBUS_UART1.3 ; also sheet 1
FIFO_B: 2.4RF_UART.3 R77.2 R106.1 ; also sheet 1
FIFOP: RF1.4 TP21.TP(-)
FIFOP1: RF3.4 TP23.TP(-)
FIFOP_A: R60.1 R67.2 WMBUS_UART0.1 WMBUS_UART1.1 ; also sheet 1
FIFOP_B: 2.4RF_UART.1 R78.2 R107.1 ; also sheet 1
N$2: R30.2 RF1.7
N$6: RF1.11 TP8.TP(-)
N$9: D14.C R45.2 U3.2(A)
N$21: R51.2 U4.2(A)
N$22: Q3.B R52.2
N$26: R50.2 RS-232.2 U4.6(VO)
N$37: RF1.13 TP4.TP(-)
N$38: R66.1 RF1.6
N$39: R67.1 RF1.8
N$40: R68.1 RF1.10
N$42: R69.1 RF1.12
N$45: R70.1 RF1.14
N$46: R71.1 RF1.16
N$50: R72.1 RF1.18
N$51: R73.1 RF1.20
N$52: R108.2 RF3.3
N$53: RF1.15 TP13.TP(-)
N$54: RF1.17 TP10.TP(-)
N$56: R77.1 RF3.6
N$57: R78.1 RF3.8
N$58: R79.1 RF3.10
N$59: R74.2 RF2.18
N$60: R80.1 RF3.12
N$61: R81.1 RF3.14
N$62: R82.1 RF3.16
N$63: R83.1 RF3.18
N$64: R84.1 RF3.20
N$65: R85.2 RF4.18
N$66: R87.1 RF4.15
N$67: RF3.11 TP25.TP(-)
N$68: RF3.13 TP24.TP(-)
N$69: RF3.15 TP27.TP(-)
N$71: RF3.17 TP26.TP(-)
N$75: R10.2 RF2.4
N$76: OK1.2(C) R88.2
N$77: C32.- D16.A U4.5(GND)
N$78: D16.C R45.1 RS-232.3
N$79: Q3.C U4.3(C)
N$80: OK1.4(COL) SL1.1
N$81: OK1.3(EMIT) SL1.2
N$82: R27.2 RF1.5
N$84: OK2.2(C) R89.2
N$85: R40.2 RF2.6
N$86: OK2.4(COL) SL2.1
N$87: OK2.3(EMIT) SL2.2
N$89: R41.1 RF2.7
N$104: R61.2 RF1.3
N$105: R60.2 RF1.9
N$106: R76.1 RF2.15
N$107: R75.1 RF2.19
N$108: R86.1 RF4.19
N$109: R107.2 RF3.9
N$110: R105.2 RF3.5
N$111: R106.2 RF3.7
N$132: J3.1 R47.1 R51.1 U3.8(VCC)
OPTO: JP5.1 R88.1 ; also sheet 1
OPTO2: JP6.1 R89.1 ; also sheet 1
PC_GND: C31.- C32.+ D14.A RS-232.5 RS-232.G1 U3.3(C)
PC_VCC: D15.A RS-232.4
PIN8: C31.+ D15.C R50.1 U4.8(VCC)
PLC_RX: JP13.2 ; also sheet 1,3,5
PLC_TX: JP12.2 ; also sheet 1,3,5
RESETCC_A: R27.1 R76.2 ; also sheet 1
RESETCC_B: R87.2 R105.1 ; also sheet 1
RF1_GPIO1: R75.2 ; also sheet 1
RF1_GPIO2: R74.1 ; also sheet 1
RF2_GPIO1: R86.2 ; also sheet 1
RF2_GPIO2: R85.1 ; also sheet 1
SFD_A: R69.2 ; also sheet 1
SFD_B: R80.2 ; also sheet 1
UART_RX: J2.1 JP12.1 JP12.4 R47.2 U3.6(VO)
UART_TX: J1.1 JP13.1 JP13.4 R52.1
VREG_EN_A: R61.1 ; also sheet 1
VREG_EN_B: R108.1 ; also sheet 1
Unconnected: EZRF.3 EZRF.4 RF2.1 RF2.3 RF2.5 RF2.8 RF2.10 RF2.11 RF2.12 RF2.13 RF2.14 RF2.16 RF2.17 RF2.20 RF4.1 RF4.3 RF4.4 RF4.5 RF4.6 RF4.7 RF4.8 RF4.10 RF4.11 RF4.12 RF4.13 RF4.14 RF4.16 RF4.17 RF4.20 RS-232.1 RS-232.6 RS-232.7 RS-232.8 RS-232.9 RS-232.G2 U3.7(VB) U4.7(VB)

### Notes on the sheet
- Isolated Energy Pulse circuitry
- Isolated RS232 Communication
- EZ-RF Connect
- MMBT5088
- 2.4 GHz RF Daughter Card Connect
- Sub 1GHz RF Daughter Card Connect
- F47187 Smart-meter EVM: MSP430 Communication modules

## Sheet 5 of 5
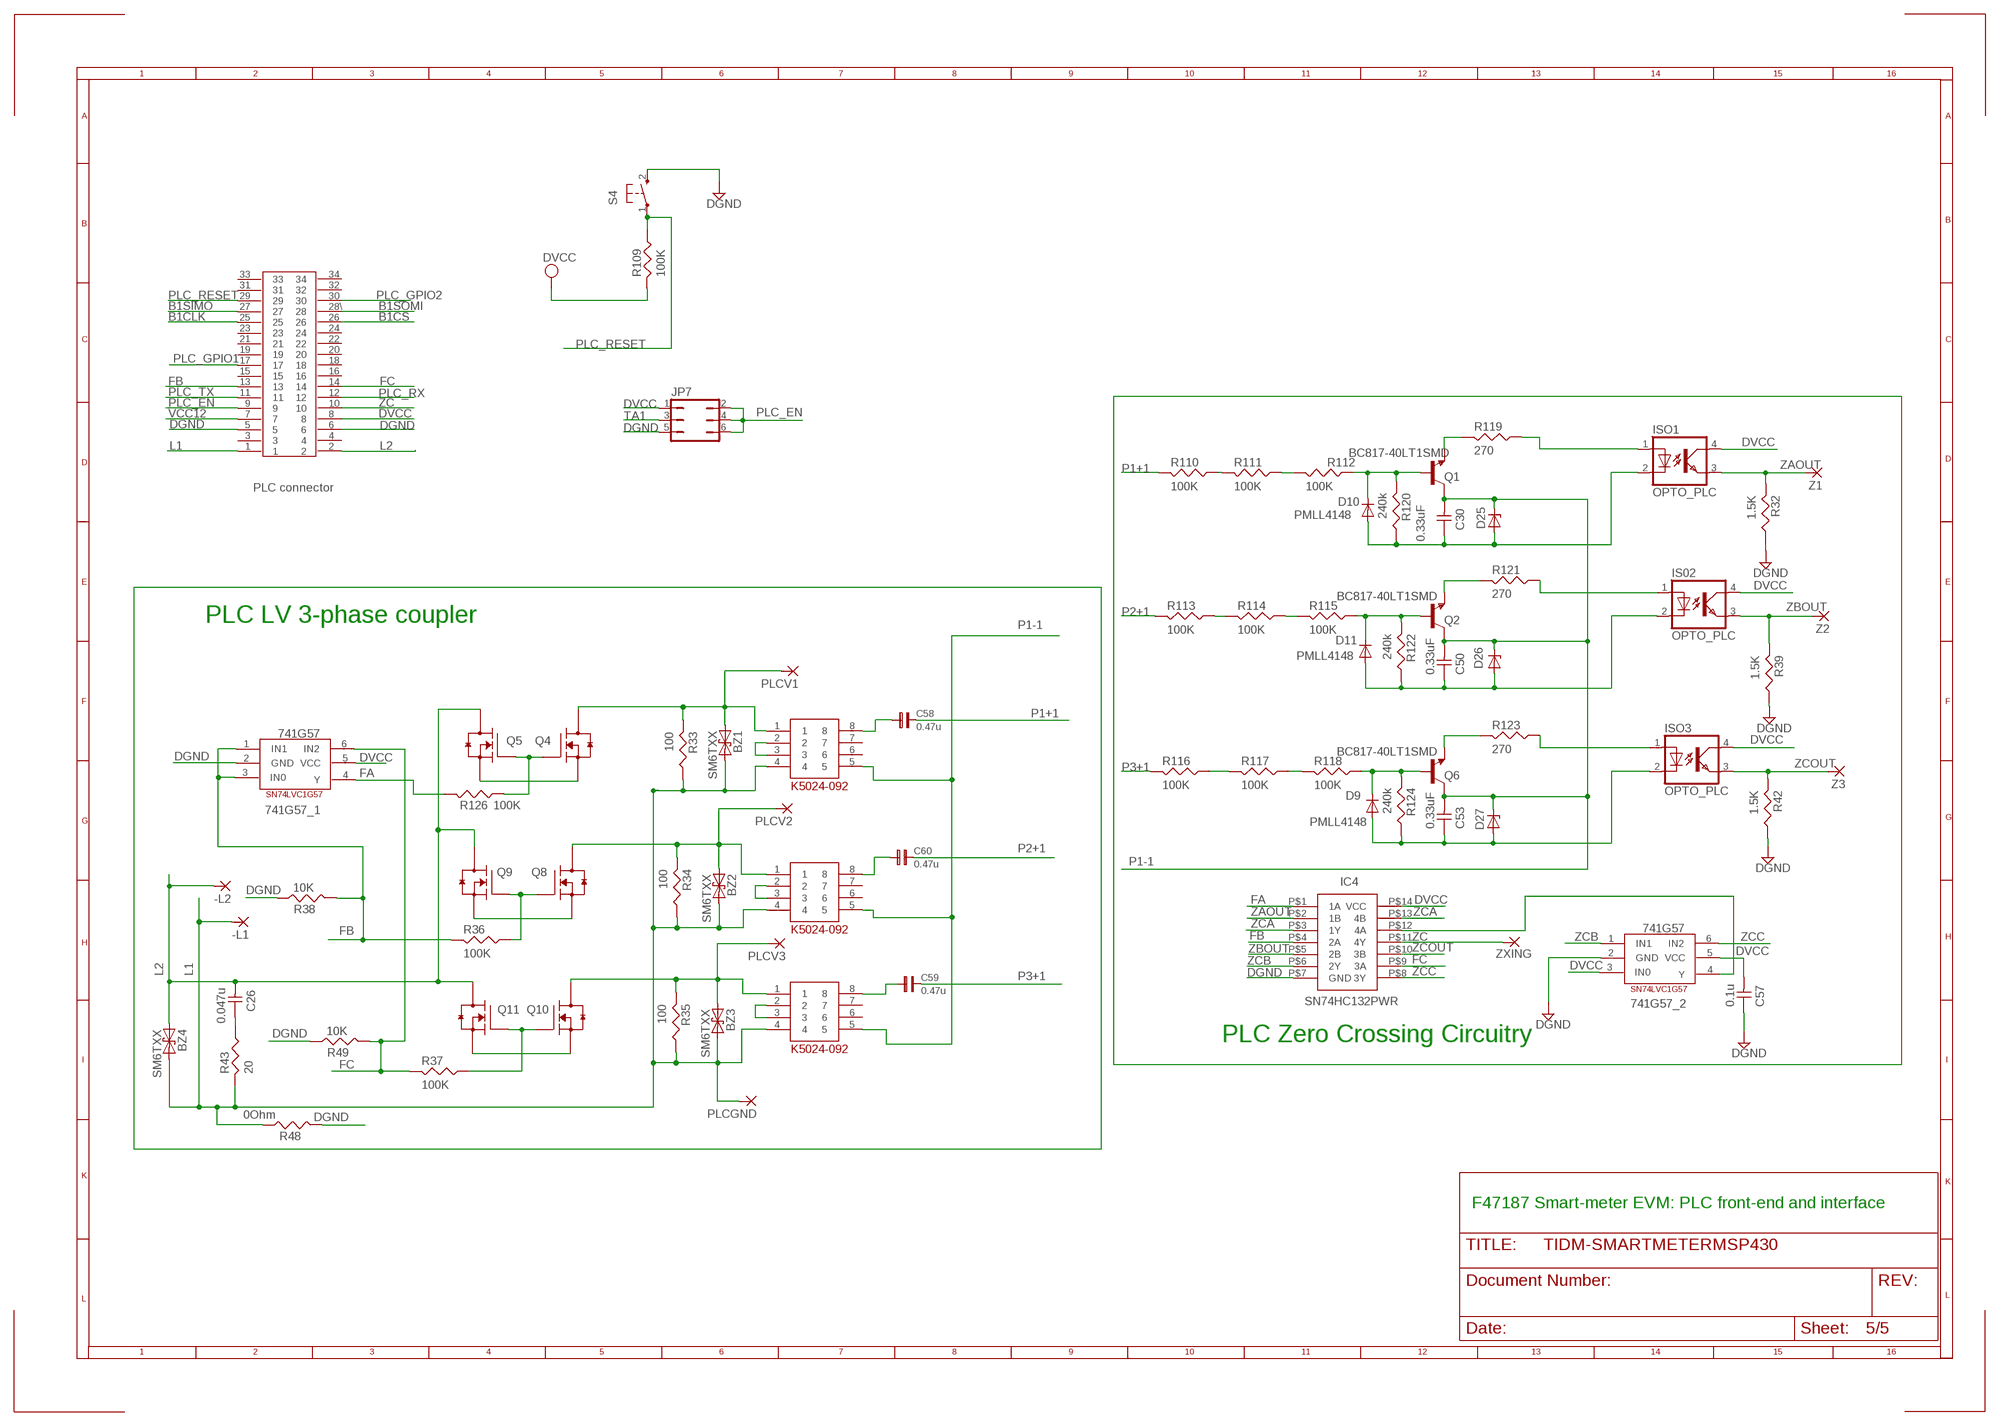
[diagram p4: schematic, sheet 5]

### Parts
741G57  SOT23-6  [SOT23-6]
741G157_1  SOT23-6  [SOT23-6]
-L1  2,54/0,8  [2,54/0,8]
-L2  2,54/0,8  [2,54/0,8]
BZ1  SM6TXX  [SOD15]
BZ2  SM6TXX  [SOD15]
BZ3  SM6TXX  [SOD15]
BZ4  SM6TXX  [SOD15]
C26  0.047u  CAP-NP0805  [C0805]
C30  0.33uF  CAP-NP0805  [C0805]
C50  0.33uF  CAP-NP0805  [C0805]
C53  0.33uF  CAP-NP0805  [C0805]
C57  0.1u  CAP-NP0805  [C0805]
C58  0.47u  C17  [C17]
C59  0.47u  C17  [C17]
C60  0.47u  C17  [C17]
D9  PMLL4148  [SOD80C]
D10  PMLL4148  [SOD80C]
D11  PMLL4148  [SOD80C]
D25  ZENER-DIODESOD80C  [SOD80C@1]
D26  ZENER-DIODESOD80C  [SOD80C@1]
D27  ZENER-DIODESOD80C  [SOD80C@1]
IS02  OPTO_PLC  [OPTOCOUPLER_FOD]
ISO1  OPTO_PLC  [OPTOCOUPLER_FOD]
ISO3  OPTO_PLC  [OPTOCOUPLER_FOD]
JP7  JP3Q  [JP3Q]
PLCGND  2,54/0,8  [2,54/0,8]
PLCV1  2,54/0,8  [2,54/0,8]
PLCV2  2,54/0,8  [2,54/0,8]
PLCV3  2,54/0,8  [2,54/0,8]
Q1  BC817-40LT1SMD  [SOT23-BEC]
Q2  BC817-40LT1SMD  [SOT23-BEC]
Q4  MOSFET-NCH_SOT-23  [SOT95P280X135-3N]
Q5  MOSFET-NCH_SOT-23  [SOT95P280X135-3N]
Q6  BC817-40LT1SMD  [SOT23-BEC]
Q8  MOSFET-NCH_SOT-23  [SOT95P280X135-3N]
Q9  MOSFET-NCH_SOT-23  [SOT95P280X135-3N]
Q10  MOSFET-NCH_SOT-23  [SOT95P280X135-3N]
Q11  MOSFET-NCH_SOT-23  [SOT95P280X135-3N]
R32  1.5K  RES0805  [R0805]
R33  100  RES0805  [R0805]
R34  100  RES0805  [R0805]
R35  100  RES0805  [R0805]
R36  100K  RES0805  [R0805]
R37  100K  RES0805  [R0805]
R38  10K  RES0805  [R0805]
R39  1.5K  RES0805  [R0805]
R42  1.5K  RES0805  [R0805]
R43  20  RES0805  [R0805]
R48  0Ohm  RES0805  [R0805]
R49  10K  RES0805  [R0805]
R109  100K  RES0805  [R0805]
R110  100K  RES0805  [R0805]
R111  100K  RES0805  [R0805]
R112  100K  RES0805  [R0805]
R113  100K  RES0805  [R0805]
R114  100K  RES0805  [R0805]
R115  100K  RES0805  [R0805]
R116  100K  RES0805  [R0805]
R117  100K  RES0805  [R0805]
R118  100K  RES0805  [R0805]
R119  270  RES0805  [R0805]
R120  240k  RES0805  [R0805]
R121  270  RES0805  [R0805]
R122  240k  RES0805  [R0805]
R123  270  RES0805  [R0805]
R124  240k  RES0805  [R0805]
R126  100K  RES0805  [R0805]
S4  PB  [PBTH]
U$1  PLC_SMB25  [PLC_SMB25]
U$2  PLC_SMB25  [PLC_SMB25]
U$3  PLC_SMB25  [PLC_SMB25]
U$10  74132  [74132]
U$14  CONN34  [CONN34]
Z1  2,54/0,8  [2,54/0,8]
Z2  2,54/0,8  [2,54/0,8]
Z3  2,54/0,8  [2,54/0,8]
ZXING  2,54/0,8  [2,54/0,8]

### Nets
B1CLK: U$14.25 ; also sheet 1
B1CS: U$14.26 ; also sheet 1
B1SIMO: U$14.27 ; also sheet 1
B1SOMI: U$14.28\ ; also sheet 1
DGND: 741G57.2(GND) 741G157_1.2(GND) C57.1 JP7.5 R32.1 R38.1 R39.1 R42.1 R48.2 R49.1 S4.2(S) U$10.P$7(GND) U$14.5 U$14.6 ; also sheet 1,3,4
DVCC: 741G57.3(IN0) 741G57.5(VCC) 741G157_1.5(VCC) C57.2 IS02.4(COL) ISO1.4(COL) ISO3.4(COL) JP7.1 R109.2 U$10.P$14(VCC) U$14.8 ; also sheet 1,3,4
FA: 741G157_1.4(Y) R126.2 U$10.P$1(1A)
FB: 741G157_1.1(IN1) 741G157_1.3(IN0) R36.2 R38.2 U$10.P$4(2A) U$14.13
FC: 741G157_1.6(IN2) R37.2 R49.2 U$10.P$9(3A) U$14.14
IT2: BZ2.P$1 PLCV2.1(P) Q8.3(D) R34.2 U$3.1
L1: -L1.1(P) BZ1.P$2 BZ2.P$2 BZ3.P$2 BZ4.P$2 PLCGND.1(P) R33.1 R34.1 R35.1 R43.2 R48.1 U$1.4 U$2.4 U$3.4 U$14.1
L2: -L2.1(P) BZ4.P$1 C26.2 Q5.3(D) Q9.3(D) Q11.3(D) U$14.2
N$1: C53.1 D9.A D27.A ISO3.2(C) R124.1
N$3: U$1.2 U$1.3
N$5: C58.1 U$1.8
N$10: C60.1 U$3.8
N$11: U$3.2 U$3.3
N$12: BZ3.P$1 PLCV3.1(P) Q10.3(D) R35.2 U$2.1
N$17: U$2.2 U$2.3
N$20: C26.1 R43.1
N$23: ISO1.1(A) R119.1
N$55: C59.1 U$2.8
N$73: D10.C Q1.B R112.1 R120.2
N$88: R110.1 R111.2
N$93: C30.1 D10.A D25.A ISO1.2(C) R120.1
N$94: Q4.1(G) Q5.1(G) R126.1
N$97: Q4.2(S) Q5.2(S)
N$98: Q8.1(G) Q9.1(G) R36.1
N$99: R117.1 R118.2
N$103: R116.1 R117.2
N$113: Q1.E R119.2
N$117: Q2.E R121.2
N$118: IS02.1(A) R121.1
N$120: Q6.E R123.2
N$121: ISO3.1(A) R123.1
N$125: R111.1 R112.2
N$128: 741G57.4(Y) U$10.P$12(4A)
N$129: BZ1.P$1 PLCV1.1(P) Q4.3(D) R33.2 U$1.1
N$130: R113.1 R114.2
N$131: Q8.2(S) Q9.2(S)
N$139: Q10.1(G) Q11.1(G) R37.1
N$140: Q10.2(S) Q11.2(S)
N$143: R114.1 R115.2
N$144: D11.C Q2.B R115.1 R122.2
N$145: D9.C Q6.B R118.1 R124.2
P1+1: C58.2 R110.2 ; also sheet 2,3
P1-1: C30.2 C50.2 C53.2 D25.C D26.C D27.C Q1.C Q2.C Q6.C U$1.5 U$2.5 U$3.5 ; also sheet 2,3
P2+1: C60.2 R113.2 ; also sheet 2
P3+1: C59.2 R116.2 ; also sheet 2
PLC_EN: JP7.2 JP7.4 JP7.6 U$14.9
PLC_GPIO1: U$14.17 ; also sheet 1
PLC_GPIO2: U$14.30 ; also sheet 1
PLC_RESET: R109.1 S4.1(P) U$14.29
PLC_RX: U$14.12 ; also sheet 1,3,4
PLC_TX: U$14.11 ; also sheet 1,3,4
TA1: JP7.3 ; also sheet 1
TEMP_1: C50.1 D11.A D26.A IS02.2(C) R122.1
VCC12: U$14.7 ; also sheet 3
ZAOUT: ISO1.3(EMIT) R32.2 U$10.P$2(1B) Z1.1(P)
ZBOUT: IS02.3(EMIT) R39.2 U$10.P$5(2B) Z2.1(P)
ZC: U$10.P$11(4Y) U$14.10 ZXING.1(P)
ZCA: U$10.P$3(1Y) U$10.P$13(4B)
ZCB: 741G57.1(IN1) U$10.P$6(2Y)
ZCC: 741G57.6(IN2) U$10.P$8(3Y)
ZCOUT: ISO3.3(EMIT) R42.2 U$10.P$10(3B) Z3.1(P)
Unconnected: U$1.6 U$1.7 U$2.6 U$2.7 U$3.6 U$3.7 U$14.3 U$14.4 U$14.15 U$14.16 U$14.18 U$14.19 U$14.20 U$14.21 U$14.22 U$14.23 U$14.24 U$14.31 U$14.32 U$14.33 U$14.34

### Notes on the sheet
- PLC connector
- PLC LV 3-phase coupler
- 741G57_1
- IC4
- SN74HC132PWR | 741G57_2
- PLC Zero Crossing Circuitry
- F47187 Smart-meter EVM: PLC front-end and interface

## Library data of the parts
2.4RF_UART EZRF_EN LED_EN PLC_GPIO PLC_UART RF1_FIFO RF1_GPIO RF2_FIFO RF2_GPIO WMBUS_UART0 WMBUS_UART1 = jumper:JP2Q: JUMPER
3_3VDC 5VDC 12VDC GND HDR0 JP1-JP4 JP9-JP11 PWR_JMP = jumper:JP2E: JUMPER
741G57 741G157_1 = 6SOT23:SOT23-6
-L1 -L2 PLCGND PLCV1-PLCV3 Z1-Z3 ZXING = wirepad:2,54/0,8: THROUGH-HOLE PAD
BZ1-BZ4 = _Emeter_Kripa:SM6TXX
C1 = SMD-CAP:C
C2 C3 C8 C11 C42 C44 = rcl:CPOL-US: POLARIZED CAPACITOR, American symbol
C4-C7 C9 C10 C12 C13 C26 C30 C43 C45 C50 C53 C57 = _MSP430:CAP-NP
C14-C25 C33-C41 = rcl:C-EU: CAPACITOR, European symbol
C28 C29 C31 C32 = rcl:CPOL-EU: POLARIZED CAPACITOR, European symbol
C58-C60 = cap-pan:C17
D1-D11 D17-D24 = FE449x EVM:PMLL4148: DIODE
D14-D16 = diode:DIODE-: DIODE
D25-D27 = diode:ZENER-DIODE: Z-Diode
DGND DVCC JP12 JP13 = jumper:JP4E: JUMPER
EZRF = susbfet:SL127L6TH
IS02 ISO1 ISO3 = _Emeter_Kripa:OPTO_PLC
J1-J3 J5 JP5 JP6 SW2_JMP = jumper:JP1E: JUMPER
JP7 = jumper:JP3Q: JUMPER
JTAG = con-ml:ML14: HARTING
L1-L4 L12 L13 = FE449x EVM:EXCELSA39: INDUCTOR
L5-L8 L14-L17 = SMD:L-US0805
LCD1 = Display-SoftBaugh2:SBLCDA4
LED1-LED3 = led:LED: LED
MSP430F47187 = TI_MSP430_v11:MSP430F471X7PZ100
OK1 OK2 = optocoupler:TIL191: TEXAS INSTRUMENTS OPTO COUPLER
Q1 Q2 Q6 = transistor-npn:BC817*: NPN Transistor
Q3 = transistor-npn:BC807*: NPN Transistor
Q4 Q5 Q8-Q11 = ipc-7351-transistor:MOSFET-NCH_
R1-R9 R11-R16 R18-R23 R25 R26 R28 R29 R31-R39 R42 R43 R45-R52 R54-R58 R62-R65 R109-R124 R126 = _MSP430:RES
R10 R27 R30 R40 R41 R60 R61 R66-R89 R105-R108 = rcl:R-EU_: RESISTOR, European symbol
R17 R24 R59 = varistor:S20K275: VARISTOR
R101-R104 = resistor:R-US_: RESISTOR, American symbol
RF1-RF4 = _MSP430:TFM-110-02-SM-D-A-K
RS-232 = con-subd:F09VP: SUB-D
S1-S4 = electricalmeter:PB: OMRON SWITCH
SL1 SL2 = con-amp-quick:M02: AMP QUICK CONNECTOR
TP4 TP8 TP10 TP13 TP20-TP27 = F20xx PIR Demo & Eval:TST_PNT
TVS1-TVS4 = FE449x EVM:SMAJ5.0CA
U3 U4 = FE449x EVM:PS8802: MOTOROLA OPTO COUPLER
U$1-U$3 = VAC_CT:PLC_SMB25
U$4 = _Emeter:AC_DC_12V
U$5 U$7 = _Emeter:PTH08080
U$6 = _Emeter:WATT_PULSE
U$8 U$9 = 74xx-little-us:741T45
U$10 = _Emeter:74132
U$14 = _Emeter_Kripa2:CONN34
X1-X7 = FE449x EVM:FFKV2: PHOENIX
XT1 = F20xx PIR Demo & Eval:CM200T
XT2 = ATC2004 Lab HW:X905: CRYSTAL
